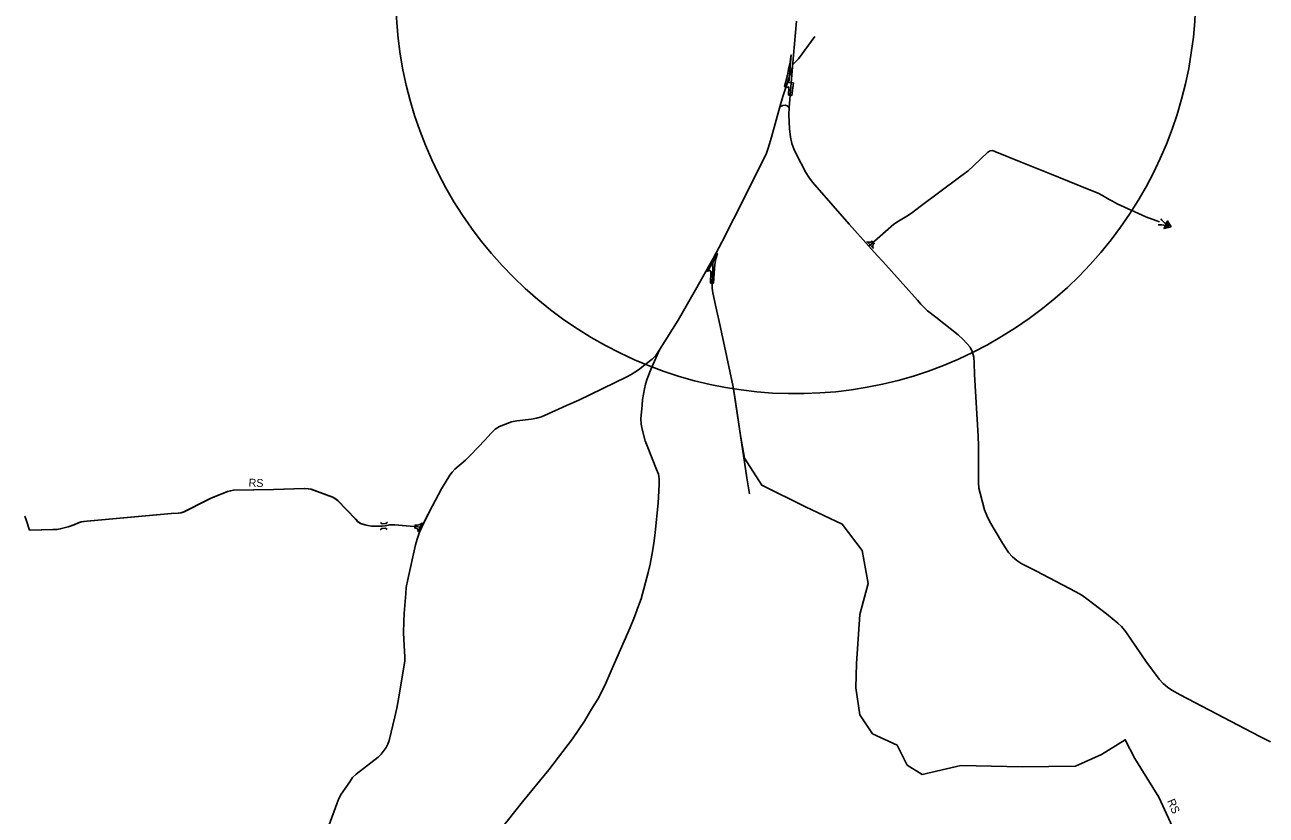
# Model space of a CAD drawing. Extents: x -546703 to -534152, y -1046534 to -1035676.
# Drawn here: x -545118 to -543567, y -1043304 to -1042315 of the extents above; entities that cross this region are included whole.
import ezdxf

# ---------------------------------------------------------------- set-up
doc = ezdxf.new("R2010")
doc.units = 0
for name, color, linetype in [('Vrstva 11', 7, 'Continuous'), ('Vrstva 22', 7, 'Continuous'), ('Vrstva 26', 7, 'Continuous'), ('Vrstva 37', 7, 'Continuous'), ('Vrstva 4', 7, 'Continuous'), ('Vrstva 7', 7, 'Continuous'), ('Vrstva 8', 7, 'Continuous')]:
    doc.layers.add(name, color=color, linetype=linetype)

msp = doc.modelspace()

# ---------------------------------------------------------------- linework, layer by layer
at = {"layer": 'Vrstva 11'}
for points in [[(-544063.4, -1042591.7), (-544032.1, -1042564.3), (-544026.3, -1042560.6), (-544016.1, -1042554.5), (-544010.1, -1042550.4), (-543999.1, -1042542.1), (-543950.1, -1042505.6), (-543939.4, -1042497.5), (-543932.8, -1042491.2), (-543914.9, -1042474.4), (-543912, -1042472.7), (-543908.8, -1042472.2), (-543905.8, -1042473.5), (-543873, -1042487), (-543837.6, -1042501.2), (-543788.5, -1042521.1), (-543777, -1042525.6), (-543771.6, -1042528.4), (-543762.9, -1042533.4), (-543759.1, -1042535.8), (-543752.9, -1042539.1), (-543717.2, -1042555), (-543704.8, -1042559.6), (-543700.2, -1042561.5)], [(-544258.2, -1042607.2), (-544259.5, -1042638.1), (-544259.4, -1042644.4), (-544258.5, -1042650.4), (-544254.1, -1042669.5), (-544248.7, -1042693.5), (-544233, -1042767.9)], [(-543998.3, -1042664.5), (-543995.6, -1042667.4), (-543990, -1042672.7), (-543979.9, -1042680.6), (-543951.7, -1042702.7), (-543945.4, -1042708.7), (-543937, -1042718.4), (-543934.1, -1042723.8), (-543932.4, -1042730.7), (-543932, -1042738.3), (-543931.3, -1042752.3), (-543926.8, -1042829.5), (-543926.4, -1042841.6), (-543926.6, -1042854.5), (-543926.3, -1042887.6), (-543925.8, -1042894.4), (-543924.4, -1042901), (-543919, -1042921.5), (-543916, -1042928.8), (-543912.2, -1042936.7), (-543905.7, -1042948.1), (-543896.2, -1042963.2), (-543888.7, -1042975), (-543884.1, -1042980.6), (-543878.6, -1042985.2), (-543872.4, -1042989.1), (-543854.7, -1042998), (-543804.8, -1043024), (-543797.2, -1043028.5), (-543790.8, -1043033), (-543782.1, -1043039.5), (-543766.3, -1043051.7), (-543752.2, -1043063.5), (-543747.8, -1043067.5), (-543742.3, -1043074.4), (-543717.1, -1043110.9), (-543700.6, -1043133.6), (-543695.7, -1043139), (-543690.3, -1043143.4), (-543684.7, -1043147.1), (-543674.4, -1043152.9), (-543574.9, -1043205.1), (-543561.2, -1043212)], [(-544325, -1042721.6), (-544335.8, -1042746), (-544340.6, -1042757.7), (-544342.7, -1042764.3), (-544344, -1042770.5), (-544346.3, -1042783.6), (-544347, -1042790.7), (-544348.5, -1042807.9), (-544348, -1042814.6), (-544346.8, -1042820.9), (-544343.1, -1042835.4), (-544340.7, -1042841.6), (-544328.9, -1042871), (-544326.5, -1042877.1), (-544325.7, -1042883), (-544325.7, -1042890), (-544325.8, -1042897.7), (-544327, -1042913.5), (-544330.7, -1042950.2), (-544332.2, -1042963.7), (-544334.8, -1042978.5), (-544336.9, -1042989.5), (-544339.5, -1043000), (-544348.2, -1043032.9), (-544351.4, -1043041.6), (-544356.4, -1043055.5), (-544361.8, -1043068.9), (-544381.2, -1043113.3), (-544392.4, -1043138.6), (-544397.8, -1043149.6), (-544402.4, -1043158.4), (-544406.8, -1043165.4), (-544411.2, -1043173.2), (-544419, -1043185.9)], [(-544233, -1042767.9), (-544231.2, -1042777.7), (-544223.7, -1042828.6), (-544216.1, -1042881.6), (-544212.5, -1042901.6)], [(-544622.1, -1042943.2), (-544656.1, -1042940.5), (-544659.4, -1042940.4), (-544662.1, -1042940.6), (-544667.7, -1042941.7), (-544672, -1042942), (-544677.4, -1042942.1), (-544684.7, -1042941.9), (-544689.1, -1042941.4), (-544693.1, -1042940.3), (-544698.5, -1042938.7), (-544701.7, -1042936.6), (-544704.8, -1042933.3), (-544727.4, -1042909.9), (-544730.4, -1042907.6), (-544733.6, -1042905.9), (-544760.7, -1042895.7), (-544763.8, -1042895.2), (-544768.7, -1042894.8), (-544807.3, -1042896.1), (-544857.2, -1042897.2), (-544861, -1042897.7), (-544864.8, -1042898.9), (-544881.5, -1042905.5), (-544886.4, -1042907.5), (-544890.4, -1042909.4), (-544919.4, -1042924.1), (-544923.2, -1042925.3), (-544926.6, -1042925.9), (-544935, -1042926.4), (-545040.7, -1042935.7), (-545044.4, -1042936.1), (-545047.7, -1042936.7), (-545051.3, -1042938), (-545056.8, -1042940.3), (-545064.1, -1042942.8), (-545074.1, -1042945.5), (-545078.2, -1042946.1), (-545083.2, -1042946.1), (-545111.4, -1042946.9)], [(-544622.2, -1042943.2), (-544625, -1042949.6), (-544628.2, -1042958.3), (-544630.1, -1042965.5), (-544639.7, -1043008.6), (-544641.7, -1043018.6), (-544642.3, -1043026.3), (-544644.4, -1043051.1), (-544644.8, -1043061.5), (-544645.1, -1043075.3), (-544644.4, -1043091.3), (-544643.4, -1043105.4), (-544643.6, -1043111.1), (-544644.7, -1043117.9), (-544650.7, -1043153.4), (-544653.5, -1043169.5), (-544655.9, -1043180.6), (-544662.9, -1043210), (-544664.6, -1043214.9), (-544667, -1043219), (-544672.9, -1043227.1), (-544677, -1043230.8), (-544704.3, -1043252.2), (-544708.7, -1043256.4), (-544712.4, -1043262), (-544723, -1043277.1), (-544725.8, -1043282.5), (-544728.5, -1043289.3), (-544738.1, -1043315.8)], [(-544419, -1043185.9), (-544434, -1043207.9), (-544463.4, -1043246.8), (-544496.2, -1043287), (-544525.3, -1043323.2)]]:
    msp.add_lwpolyline(points, dxfattribs=at)
for points in [[(-544062, -1042590.4), (-544065.7, -1042586.3), (-544064.1, -1042586.8), (-544062.7, -1042586.9), (-544061.2, -1042586.7), (-544059.3, -1042585.7), (-544056.7, -1042588.2), (-544057.9, -1042589.6), (-544058.6, -1042591.3), (-544058.6, -1042592.6), (-544058.2, -1042594.5)], [(-544257.8, -1042638.1), (-544256.4, -1042619.5), (-544255.5, -1042612), (-544254.8, -1042607.8), (-544252.7, -1042601.2), (-544256.4, -1042608.2), (-544265, -1042623.5), (-544263.8, -1042622.5), (-544262.8, -1042622.3), (-544261.9, -1042622.5), (-544261.4, -1042623.1), (-544261, -1042624.3), (-544261.3, -1042638.1)], [(-544624, -1042942.3), (-544626.9, -1042948.9), (-544627.1, -1042946.9), (-544627.8, -1042945.6), (-544628.8, -1042944.8), (-544631, -1042944.2), (-544630.7, -1042940.7), (-544628, -1042940.7), (-544625.8, -1042940.2), (-544623.8, -1042939.4), (-544622, -1042938.3)]]:
    msp.add_lwpolyline(points, close=True, dxfattribs=at)
at = {"layer": 'Vrstva 22'}
for points in [[(-544258.2, -1042607.2), (-544280.1, -1042646.7), (-544301.6, -1042684.5), (-544325, -1042721.6), (-544329.8, -1042728.6), (-544334.5, -1042733.3), (-544341.2, -1042738.7), (-544351.5, -1042746.7), (-544360.4, -1042752.2), (-544366.6, -1042755.6), (-544426.1, -1042784.4), (-544441.2, -1042791.2), (-544451.2, -1042795.7), (-544472.5, -1042805.2), (-544479, -1042807.1), (-544485.3, -1042808.1), (-544503.6, -1042810.4), (-544510, -1042811.7), (-544525.3, -1042817.5), (-544530.7, -1042820.8), (-544535.8, -1042826.2), (-544542.9, -1042834.2), (-544561.4, -1042853.4), (-544567.7, -1042859.4), (-544581, -1042870.9), (-544584.4, -1042874.5), (-544587.3, -1042878.4), (-544597.6, -1042895.4), (-544608.8, -1042916.8), (-544622.4, -1042943.2)], [(-544258.2, -1042607.2), (-544259.5, -1042638.1), (-544259.4, -1042644.4), (-544258.5, -1042650.4), (-544254.1, -1042669.5), (-544248.7, -1042693.5), (-544233, -1042767.9), (-544223.7, -1042828.6), (-544218.7, -1042856.9)], [(-544218.7, -1042856.9), (-544197.4, -1042891), (-544142.6, -1042917.7), (-544096.6, -1042939.4), (-544071.6, -1042972.5), (-544064.3, -1043013.7), (-544074.8, -1043052.4), (-544078.8, -1043113.7), (-544079.7, -1043144.3), (-544074.8, -1043178.2), (-544058.7, -1043201.6), (-544028, -1043216.1), (-544015.5, -1043240.8), (-543997, -1043252.8), (-543948.6, -1043241.6), (-543871.9, -1043243.2), (-543805, -1043242.4), (-543772.7, -1043227.8), (-543742.9, -1043209.3), (-543730.8, -1043232.7), (-543700.9, -1043281.1), (-543676.7, -1043333.5)], [(-544622.4, -1042943.2), (-544656.5, -1042940.5), (-544659.8, -1042940.4), (-544662.5, -1042940.6), (-544668.1, -1042941.7), (-544672.4, -1042942), (-544677.8, -1042942.1), (-544685.1, -1042941.9), (-544689.5, -1042941.4), (-544693.5, -1042940.3), (-544698.9, -1042938.7), (-544702.1, -1042936.6), (-544705.2, -1042933.3), (-544727.8, -1042909.9), (-544730.8, -1042907.6), (-544734, -1042905.9), (-544761.1, -1042895.7), (-544764.2, -1042895.2), (-544769.1, -1042894.8), (-544807.7, -1042896.1), (-544857.6, -1042897.2), (-544861.4, -1042897.7), (-544865.2, -1042898.9), (-544881.9, -1042905.5), (-544886.8, -1042907.5), (-544890.8, -1042909.4), (-544919.8, -1042924.1), (-544923.6, -1042925.3), (-544927, -1042925.9), (-544935.4, -1042926.4), (-545041.1, -1042935.7), (-545044.8, -1042936.1), (-545048.1, -1042936.7), (-545051.7, -1042938), (-545057.2, -1042940.3), (-545064.5, -1042942.8), (-545074.5, -1042945.5), (-545078.6, -1042946.1), (-545083.6, -1042946.1), (-545112.6, -1042947), (-545116.8, -1042934.1), (-545118.5, -1042929.5)]]:
    msp.add_lwpolyline(points, dxfattribs=at)
at = {"layer": 'Vrstva 26'}
msp.add_arc((-544154.9, -1042276.4), 500, 85.1835, 19.2198, dxfattribs=at)
at = {"layer": 'Vrstva 37'}
for points in [[(-543691.7, -1042563.7), (-543693.7, -1042562.6), (-543695.6, -1042561.2), (-543697.2, -1042559.5), (-543698.5, -1042557.7)], [(-543692.8, -1042566.2), (-543695, -1042565.5), (-543697.3, -1042565.1), (-543699.6, -1042565), (-543701.8, -1042565.3)]]:
    msp.add_lwpolyline(points, dxfattribs=at)
for points in [[(-543685.7, -1042567.9), (-543694.4, -1042569.8), (-543690.2, -1042560.2)], [(-543687.9, -1042566.9), (-543692, -1042567.8), (-543690, -1042563.2)], [(-543689.4, -1042566.2), (-543690.3, -1042566.4), (-543689.9, -1042565.4)]]:
    msp.add_lwpolyline(points, close=True, dxfattribs=at)
at = {"layer": 'Vrstva 4'}
msp.add_lwpolyline([(-544153.7, -1042310.3), (-544157.6, -1042353), (-544158.9, -1042367.9), (-544160.6, -1042387.6)], dxfattribs=at)
at = {"layer": 'Vrstva 7'}
for points in [[(-544130.9, -1042329.8), (-544151.4, -1042357.6), (-544158.3, -1042364.6)], [(-544158.9, -1042367.9), (-544171.1, -1042404.7), (-544174.9, -1042417.8), (-544185.2, -1042455.6), (-544189.4, -1042469.5), (-544192, -1042476.7), (-544195.5, -1042484.1), (-544217.7, -1042528.6), (-544247.4, -1042586.8), (-544258.2, -1042607.2), (-544280.1, -1042646.7), (-544301.6, -1042684.5), (-544325, -1042721.6), (-544329.8, -1042728.6), (-544334.5, -1042733.3), (-544341.2, -1042738.7), (-544351.5, -1042746.7), (-544360.4, -1042752.2), (-544366.6, -1042755.6), (-544426.1, -1042784.4), (-544441.2, -1042791.2), (-544451.2, -1042795.7), (-544472.5, -1042805.2), (-544479, -1042807.1), (-544485.3, -1042808.1), (-544503.6, -1042810.4), (-544510, -1042811.7), (-544525.3, -1042817.5), (-544530.7, -1042820.8), (-544535.8, -1042826.2), (-544542.9, -1042834.2), (-544561.4, -1042853.4), (-544567.7, -1042859.4), (-544581, -1042870.9), (-544584.4, -1042874.5), (-544587.3, -1042878.4), (-544597.6, -1042895.4), (-544608.8, -1042916.8), (-544619.1, -1042936.8), (-544622.1, -1042943.2), (-544622.3, -1042943.4)], [(-544160.6, -1042387.6), (-544162.9, -1042418.5), (-544163.4, -1042427.7), (-544163.2, -1042436.4), (-544162.5, -1042445), (-544161.2, -1042455.4), (-544159.6, -1042463.6), (-544157.4, -1042470.3), (-544154.2, -1042476.5), (-544142.3, -1042499.9), (-544138.6, -1042505.7), (-544133.8, -1042511.7), (-544088.2, -1042564.4), (-544063.4, -1042591.7), (-544052.9, -1042603.4), (-544046, -1042611.1), (-544002.7, -1042659.6), (-543998.3, -1042664.5)], [(-544174.9, -1042417.8), (-544170.9, -1042415.9), (-544168.2, -1042415.7), (-544165.7, -1042416.5), (-544162.9, -1042418.5)]]:
    msp.add_lwpolyline(points, dxfattribs=at)
msp.add_lwpolyline([(-544157.6, -1042387.8), (-544159.8, -1042403.6), (-544163.8, -1042402.9), (-544163.3, -1042393.5), (-544163.6, -1042392.9), (-544164, -1042392.7), (-544164.6, -1042392.9), (-544165.3, -1042393.4), (-544169, -1042392), (-544165.3, -1042377.8), (-544163.7, -1042370.3), (-544162.4, -1042364.4), (-544160.6, -1042352.7), (-544161.9, -1042367.7), (-544163.6, -1042387.3)], close=True, dxfattribs=at)
at = {"layer": 'Vrstva 8'}
for points in [[(-544674.1, -1042946.5), (-544672.1, -1042944.9), (-544667.7, -1042944.7), (-544665.5, -1042946.3)], [(-544673.8, -1042937.5), (-544671.7, -1042939.1), (-544667.2, -1042938.8), (-544665.3, -1042937.1)]]:
    msp.add_lwpolyline(points, dxfattribs=at)

# ---------------------------------------------------------------- texts
at = {"layer": 'Vrstva 22'}
for rotation, p in [(358.0793, (-544838.9, -1042892.6)), (293.1991, (-543690.7, -1043285.7))]:
    msp.add_text('RS', height=10, rotation=rotation, dxfattribs=at).set_placement(p)

doc.saveas('drawing.dxf')
